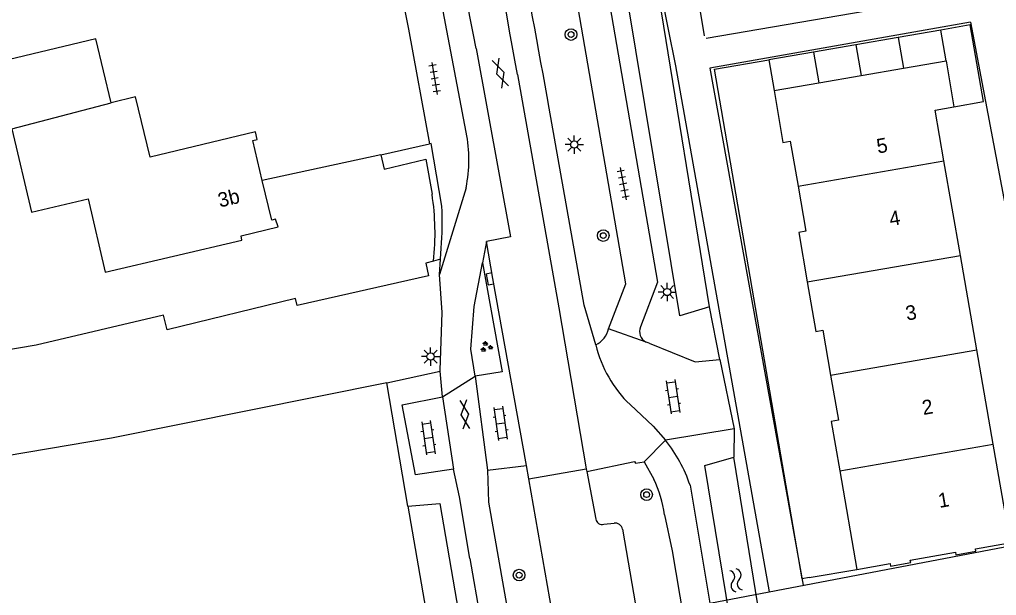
# Model space of a CAD drawing. Extents: x 136000 to 141000, y 400494 to 402006.
# Drawn here: x 137911.7 to 137978.9, y 401593.2 to 401632.8 of the extents above; entities that cross this region are included whole.
import ezdxf

# ---------------------------------------------------------------- set-up
doc = ezdxf.new("R2010")
doc.units = 0
for name, color, linetype in [('gg-afsc-erfafscheiding', 7, 'Continuous'), ('gg-afsc-hekwerk', 7, 'Continuous'), ('gg-anno-huisnummerreeks BGT', 7, 'Continuous'), ('gg-bbg-bijgebouw', 7, 'Continuous'), ('gg-bbg-hoofdgebouw', 7, 'Continuous'), ('gg-bbg-tussenscheiding', 7, 'Continuous'), ('gg-knt-bronhoudergrens', 7, 'Continuous'), ('gg-knt-plantopografie kant verharding', 7, 'Continuous'), ('gg-knt-verharding', 7, 'Continuous'), ('gg-knt-verharding nz', 7, 'Continuous'), ('gg-kntw-bovenkant insteek waterloop', 7, 'Continuous'), ('gt-grn-groengrens', 7, 'Continuous'), ('gt-grn-vlakafsluiter', 7, 'Continuous'), ('gt-grn-weggrens', 7, 'Continuous'), ('gt-symb-boom', 7, 'Continuous'), ('gt-symb-gesloten verharding', 7, 'Continuous'), ('gt-symb-groenvak', 7, 'Continuous'), ('gt-symb-klinker verharding', 7, 'Continuous'), ('gt-symb-kolk', 7, 'Continuous'), ('gt-symb-lichtmast', 7, 'Continuous'), ('gt-symb-tegel verharding', 7, 'Continuous'), ('gt-symb-watersymbool', 7, 'Continuous')]:
    doc.layers.add(name, color=color, linetype=linetype)

# ---------------------------------------------------------------- blocks, each defined once
blk = doc.blocks.new('gt0-TEG1')
at = {"layer": 'gt-symb-tegel verharding'}
for p, q in [((-1.125, 0), (1.125, 0)), ((-0.9, -0.25), (-0.9, 0.25)), ((-0.45, -0.25), (-0.45, 0.25)), ((0, -0.25), (0, 0.25)), ((0.45, -0.25), (0.45, 0.25)), ((0.9, -0.25), (0.9, 0.25))]:
    blk.add_line(p, q, dxfattribs=at)
blk = doc.blocks.new('gt0-LMAST')
at = {"layer": 'gt-symb-lichtmast'}
for p, q in [((-0.182, 0.173), (-0.447, 0.438)), ((-0.005, 0.246), (-0.005, 0.621)), ((0.172, 0.173), (0.437, 0.438)), ((-0.255, -0.004), (-0.63, -0.004)), ((-0.182, -0.181), (-0.447, -0.446)), ((-0.005, -0.254), (-0.005, -0.629)), ((0.437, -0.446), (0.172, -0.181)), ((0.245, -0.004), (0.62, -0.004))]:
    blk.add_line(p, q, dxfattribs=at)
blk.add_circle((-0.005, -0.004), 0.25, dxfattribs=at)
blk = doc.blocks.new('gt0-GESVH1')
at = {"layer": 'gt-symb-gesloten verharding'}
for p, q in [((-0.992, -0.261), (0.008, 0.239)), ((0.008, -0.261), (-0.992, 0.239)), ((0.008, 0.239), (1.008, -0.261)), ((1.008, 0.239), (0.008, -0.261))]:
    blk.add_line(p, q, dxfattribs=at)
blk = doc.blocks.new('gt0-BOOM')
at = {"layer": 'gt-symb-boom'}
for radius in [0.4, 0.2]:
    blk.add_circle((0, 0), radius, dxfattribs=at)
blk = doc.blocks.new('gt0-KL1')
at = {"layer": 'gt-symb-klinker verharding'}
for p, q in [((-1.15, 0.3), (1.15, 0.3)), ((-1, -0.3), (-1, 0.3)), ((-0.5, 0.3), (-0.5, 0.45)), ((0, -0.3), (0, 0.3)), ((0.5, 0.3), (0.5, 0.45)), ((1, -0.3), (1, 0.3)), ((-1.15, -0.3), (1.15, -0.3)), ((-0.5, -0.45), (-0.5, -0.3)), ((0.5, -0.45), (0.5, -0.3))]:
    blk.add_line(p, q, dxfattribs=at)
blk = doc.blocks.new('gt0-GRVAK')
at = {"layer": 'gt-symb-groenvak'}
for p, q in [((-0.11, 0.189), (-0.228, 0.24)), ((-0.182, 0.153), (0.088, 0.153)), ((-0.091, 0.211), (-0.156, 0.322)), ((-0.047, 0.214), (-0.047, 0.393)), ((-0.004, 0.211), (0.061, 0.322)), ((0.015, 0.189), (0.133, 0.24)), ((0.262, -0.052), (0.197, 0.059)), ((0.305, -0.049), (0.305, 0.13)), ((0.349, -0.052), (0.414, 0.059)), ((-0.245, -0.228), (-0.363, -0.177)), ((-0.318, -0.264), (-0.047, -0.264)), ((-0.226, -0.206), (-0.291, -0.095)), ((-0.183, -0.203), (-0.183, -0.024)), ((-0.139, -0.206), (-0.074, -0.095)), ((-0.12, -0.228), (-0.002, -0.177)), ((0.243, -0.074), (0.125, -0.023)), ((0.17, -0.11), (0.441, -0.11)), ((0.368, -0.074), (0.486, -0.023))]:
    blk.add_line(p, q, dxfattribs=at)
blk = doc.blocks.new('gt0-KOLK')
at = {"layer": 'gt-symb-kolk'}
blk.add_lwpolyline([(0, 0), (0.375, 0), (0.375, 0.4), (-0.375, 0.4), (-0.375, 0), (0, 0)], dxfattribs=at)
blk = doc.blocks.new('gt0-WA')
at = {"layer": 'gt-symb-watersymbool'}
for centre, start, end in [((-0.323, 0.022), 28.07249, 151.92751), ((0.427, 0.422), 208.07248, 331.92751), ((-0.323, -0.428), 28.07249, 151.92751), ((0.427, -0.028), 208.07248, 331.92751)]:
    blk.add_arc(centre, 0.425, start, end, dxfattribs=at)

msp = doc.modelspace()

# ---------------------------------------------------------------- linework, layer by layer
at = {"layer": 'gg-afsc-erfafscheiding'}
msp.add_line((137966.06, 401594.399), (137969.323, 401594.961), dxfattribs=at)
msp.add_lwpolyline([(137912.888, 401610.381), (137910.438, 401609.983), (137907.08, 401624.313), (137910.382, 401625.087)], dxfattribs=at)
at = {"layer": 'gg-afsc-hekwerk'}
msp.add_lwpolyline([(137930.707, 401613.611), (137921.883, 401611.435), (137921.643, 401612.459), (137912.888, 401610.381)], dxfattribs=at)
at = {"layer": 'gg-bbg-bijgebouw'}
msp.add_lwpolyline([(137918.035, 401627.072), (137916.985, 401631.468), (137909.296, 401629.631), (137910.382, 401625.087)], dxfattribs=at)
at = {"layer": 'gg-bbg-hoofdgebouw'}
for p, q in [((137972.166, 401631.564), (137969.259, 401631.061)), ((137975.102, 401632.072), (137972.166, 401631.564)), ((137969.259, 401631.061), (137966.352, 401630.558)), ((137966.352, 401630.558), (137963.279, 401630.026)), ((137963.279, 401630.026), (137963.638, 401627.918)), ((137976.45, 401616.57), (137975.321, 401623.074)), ((137977.578, 401610.073), (137976.45, 401616.57)), ((137978.706, 401603.577), (137977.578, 401610.073)), ((137968.154, 401601.745), (137969.323, 401594.961))]:
    msp.add_line(p, q, dxfattribs=at)
for points in [[(137976.011, 401626.789), (137978.048, 401627.155), (137977.13, 401632.423), (137975.102, 401632.072)], [(137928.434, 401621.724), (137927.78, 401624.461), (137928.085, 401624.546), (137927.955, 401625.064), (137920.709, 401623.331), (137919.718, 401627.474), (137918.035, 401627.072)], [(137963.638, 401627.918), (137964.248, 401624.342), (137964.747, 401624.428), (137965.282, 401621.33)], [(137975.321, 401623.074), (137974.716, 401626.557), (137976.011, 401626.789)], [(137911.21, 401625.281), (137912.553, 401619.546), (137916.448, 401620.458), (137917.628, 401615.414), (137927.032, 401617.615), (137926.974, 401617.904), (137929.517, 401618.533), (137929.351, 401619.051), (137929.088, 401618.988), (137928.434, 401621.724)], [(137965.282, 401621.33), (137965.817, 401618.233), (137965.33, 401618.145), (137965.914, 401614.74)], [(137965.914, 401614.74), (137966.497, 401611.335), (137966.993, 401611.421), (137967.528, 401608.328)], [(137967.528, 401608.328), (137968.062, 401605.235), (137967.569, 401605.139), (137968.154, 401601.745)], [(137969.323, 401594.961), (137971.61, 401595.36), (137971.642, 401595.179), (137973.039, 401595.425), (137973.008, 401595.604), (137976.111, 401596.146), (137976.141, 401595.973), (137977.51, 401596.215), (137977.48, 401596.385), (137983.184, 401597.381), (137983.098, 401597.873), (137979.799, 401597.285), (137978.706, 401603.577)]]:
    msp.add_lwpolyline(points, dxfattribs=at)
at = {"layer": 'gg-bbg-tussenscheiding'}
for p, q in [((137972.166, 401631.564), (137972.53, 401629.447)), ((137975.467, 401629.952), (137975.102, 401632.072)), ((137969.259, 401631.061), (137969.623, 401628.947)), ((137966.352, 401630.558), (137966.715, 401628.447)), ((137969.623, 401628.947), (137972.53, 401629.447)), ((137972.53, 401629.447), (137975.467, 401629.952)), ((137975.467, 401629.952), (137976.011, 401626.789)), ((137966.715, 401628.447), (137969.623, 401628.947)), ((137963.638, 401627.918), (137966.715, 401628.447)), ((137911.21, 401625.281), (137918.035, 401627.072)), ((137965.282, 401621.33), (137975.321, 401623.074)), ((137965.914, 401614.74), (137976.45, 401616.57)), ((137967.528, 401608.328), (137977.578, 401610.073)), ((137968.154, 401601.745), (137978.706, 401603.577))]:
    msp.add_line(p, q, dxfattribs=at)
at = {"layer": 'gg-knt-bronhoudergrens'}
msp.add_lwpolyline([(137936.993, 401607.793), (137918.069, 401603.99), (137899.215, 401600.795), (137896.666, 401600.542)], dxfattribs=at)
at = {"layer": 'gg-knt-plantopografie kant verharding'}
for p, q in [((137958.856, 401631.675), (137953.807, 401661.522)), ((137978.355, 401634.817), (137958.954, 401631.48)), ((137977.151, 401632.611), (137959.217, 401629.446)), ((137977.151, 401632.611), (137983.788, 401597.329)), ((137963.328, 401593.408), (137956.887, 401629.604)), ((137959.217, 401629.446), (137965.628, 401593.876)), ((137959.22, 401592.642), (137983.788, 401597.329))]:
    msp.add_line(p, q, dxfattribs=at)
msp.add_lwpolyline([(137956.887, 401629.604), (137952.664, 401650.546), (137952.218, 401652.545), (137951.83, 401653.881), (137951.177, 401656.389), (137950.331, 401659.075), (137949.399, 401661.212)], dxfattribs=at)
at = {"layer": 'gg-knt-verharding'}
for p, q in [((137936.579, 401623.494), (137939.94, 401624.245)), ((137942.448, 401621.224), (137940.623, 401615.243)), ((137943.851, 401617.527), (137943.572, 401616.054)), ((137940.685, 401616.296), (137940.731, 401617.063)), ((137940.685, 401616.296), (137940.202, 401616.178)), ((137940.623, 401615.243), (137940.685, 401616.296)), ((137954.835, 401610.597), (137952.237, 401611.521)), ((137955.043, 401610.523), (137954.835, 401610.597)), ((137959.907, 401609.394), (137960.9, 401604.633)), ((137940.826, 401606.846), (137940.678, 401608.593)), ((137943.065, 401608.252), (137943.928, 401601.784)), ((137940.826, 401606.846), (137941.594, 401601.858)), ((137960.9, 401604.633), (137956.171, 401603.844)), ((137943.928, 401601.784), (137946.603, 401602.119)), ((137946.76, 401601.199), (137946.603, 401602.119)), ((137954.705, 401602.369), (137955.361, 401601.176)), ((137943.928, 401601.784), (137944.001, 401599.598)), ((137946.76, 401601.199), (137950.718, 401601.872)), ((137950.718, 401601.872), (137950.764, 401601.707)), ((137950.764, 401601.707), (137951.37, 401598.426)), ((137957.855, 401600.749), (137959.22, 401592.642)), ((137944.001, 401599.598), (137947.295, 401580.773)), ((137956.095, 401598.709), (137956.624, 401596.244)), ((137951.922, 401598.067), (137952.637, 401598.134)), ((137956.624, 401596.244), (137958.787, 401583.372)), ((137942.71, 401595.71), (137955.74, 401521.282))]:
    msp.add_line(p, q, dxfattribs=at)
for points in [[(137942.461, 401625.036), (137940.244, 401636.649), (137938.433, 401645.965), (137936.328, 401656.277), (137932.589, 401672.987), (137932.577, 401673.206)], [(137934.692, 401650.955), (137936.474, 401642.178), (137938.479, 401632.133), (137939.94, 401624.245)], [(137949.745, 401648.773), (137955.606, 401614.715), (137954.453, 401611.654)], [(137952.237, 401611.521), (137953.444, 401614.609), (137947.889, 401646.77)], [(137951.375, 401610.407), (137950.567, 401613.137), (137948.167, 401626.703)], [(137940.785, 401619.95), (137940.06, 401624.266), (137939.94, 401624.245)], [(137936.827, 401622.491), (137939.674, 401623.195), (137940.109, 401620.773)], [(137946.603, 401602.119), (137944.291, 401614.987), (137943.851, 401617.527)], [(137940.202, 401616.178), (137939.69, 401616.042), (137939.862, 401615.157), (137930.822, 401613.128), (137930.707, 401613.611)], [(137943.065, 401608.252), (137942.787, 401610.105), (137943.009, 401613.042), (137943.572, 401616.054)], [(137943.572, 401616.054), (137944.922, 401608.553), (137943.065, 401608.252)], [(137940.678, 401608.593), (137940.671, 401608.681), (137940.803, 401612.643), (137940.623, 401615.243)], [(137955.043, 401610.523), (137958.21, 401609.252), (137959.907, 401609.394)], [(137941.594, 401601.858), (137938.972, 401601.458), (137938.045, 401606.284), (137940.826, 401606.846)], [(137953.73, 401606.296), (137955.31, 401604.809), (137956.171, 401603.844)], [(137950.764, 401601.707), (137954.037, 401602.387), (137954.096, 401602.267), (137954.705, 401602.369)], [(137942.71, 401595.71), (137941.999, 401599.953), (137941.594, 401601.858)], [(137949.373, 401586.296), (137948.38, 401592.013), (137946.76, 401601.199)], [(137953.206, 401597.734), (137954.115, 401592.532), (137955.8, 401582.708)]]:
    msp.add_lwpolyline(points, dxfattribs=at)
for centre, radius, start, end in [((136946.771, 401448.506), 1017.127, 10.090092, 11.527453), ((137932.913, 401623.163), 9.73, 348.50794, 11.10127), ((137923.259, 401618.134), 17.055, 353.41612, 8.90283), ((137921.508, 401618.867), 19.307, 354.63996, 3.2169), ((137950.699, 401611.82), 1.566, 295.54956, 348.98588), ((137955.211, 401611.33), 0.824, 156.88423, 242.8555), ((137959.586, 401612.381), 8.445, 193.51573, 226.09703), ((137948.345, 401597.58), 10.024, 18.42865, 38.67288), ((137948.547, 401597.806), 7.602, 6.82249, 26.31587), ((137951.801, 401598.485), 0.435, 187.76491, 286.15817), ((137952.729, 401597.66), 0.483, 8.80897, 100.97754)]:
    msp.add_arc(centre, radius, start, end, dxfattribs=at)
at = {"layer": 'gg-knt-verharding nz'}
for points in [[(137943.141, 401630.806), (137945.508, 401617.855), (137943.851, 401617.527)], [(137945.981, 401629.023), (137948.841, 401612.955), (137950.718, 401601.872)]]:
    msp.add_lwpolyline(points, dxfattribs=at)
for centre, radius, start, end in [((136145.633, 401282.114), 1831.017, 10.978255, 11.929262), ((137074.99, 401473.734), 884.725, 10.109038, 12.188098)]:
    msp.add_arc(centre, radius, start, end, dxfattribs=at)
at = {"layer": 'gg-kntw-bovenkant insteek waterloop'}
for p, q in [((137959.199, 401613.018), (137954.757, 401640.372)), ((137957.162, 401612.408), (137952.586, 401640.019)), ((137959.199, 401613.018), (137957.162, 401612.408)), ((137958.868, 401602.108), (137960.876, 401602.691)), ((137974.186, 401509.676), (137958.868, 401602.108)), ((137938.451, 401599.318), (137952.459, 401517.688))]:
    msp.add_line(p, q, dxfattribs=at)
for points in [[(137976.365, 401510.046), (137966.124, 401570.369), (137960.876, 401602.691)], [(137938.451, 401599.318), (137940.655, 401599.486), (137954.628, 401518.063)]]:
    msp.add_lwpolyline(points, dxfattribs=at)
at = {"layer": 'gt-grn-groengrens'}
for p, q in [((137959.907, 401609.394), (137959.199, 401613.018)), ((137936.993, 401607.793), (137940.678, 401608.593)), ((137938.451, 401599.318), (137936.993, 401607.793)), ((137960.9, 401604.633), (137960.876, 401602.691))]:
    msp.add_line(p, q, dxfattribs=at)
at = {"layer": 'gt-grn-vlakafsluiter'}
for q in [(137928.434, 401621.724), (137936.827, 401622.491)]:
    msp.add_line((137936.579, 401623.494), q, dxfattribs=at)
msp.add_lwpolyline([(137966.06, 401594.399), (137965.578, 401594.315), (137959.535, 401629.377), (137963.279, 401630.026)], dxfattribs=at)
at = {"layer": 'gt-grn-weggrens'}
for p, q in [((137940.826, 401606.846), (137943.065, 401608.252)), ((137954.705, 401602.369), (137956.171, 401603.844))]:
    msp.add_line(p, q, dxfattribs=at)

# ---------------------------------------------------------------- block references
at = {"layer": 'gt-symb-boom'}
for p in [(137949.668, 401631.762), (137951.889, 401617.929), (137954.869, 401600.105), (137946.098, 401594.569)]:
    msp.add_blockref('gt0-BOOM', p, dxfattribs=at)
at = {"layer": 'gt-symb-gesloten verharding'}
for p, rotation in [((137944.798, 401629.094), 108.59797779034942), ((137942.354, 401605.611), 95.79610065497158)]:
    msp.add_blockref('gt0-GESVH1', p, dxfattribs=dict(at, rotation=rotation))
at = {"layer": 'gt-symb-groenvak'}
msp.add_blockref('gt0-GRVAK', (137943.834, 401610.269), dxfattribs=at)
at = {"layer": 'gt-symb-klinker verharding'}
for p, rotation in [((137956.686, 401606.841), -81.78079075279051), ((137944.819, 401605.01), -81.78079075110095), ((137939.858, 401604.017), -81.78079075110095)]:
    msp.add_blockref('gt0-KL1', p, dxfattribs=dict(at, rotation=rotation))
at = {"layer": 'gt-symb-kolk', "rotation": 100.1893600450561}
msp.add_blockref('gt0-KOLK', (137944.291, 401614.987), dxfattribs=at)
at = {"layer": 'gt-symb-lichtmast'}
for p in [(137949.9, 401624.194), (137956.29, 401614.05), (137940.017, 401609.605)]:
    msp.add_blockref('gt0-LMAST', p, dxfattribs=at)
at = {"layer": 'gt-symb-tegel verharding'}
for p, rotation in [((137940.292, 401628.738), 99.37757912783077), ((137953.258, 401621.502), -79.16208955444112)]:
    msp.add_blockref('gt0-TEG1', p, dxfattribs=dict(at, rotation=rotation))
at = {"layer": 'gt-symb-watersymbool', "rotation": 106.0241096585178}
msp.add_blockref('gt0-WA', (137961.032, 401594.16), dxfattribs=at)

# ---------------------------------------------------------------- texts
at = {"layer": 'gg-anno-huisnummerreeks BGT'}
for s, rotation, p in [('5', 9.9, (137970.78, 401623.571)), ('3b', 13.5, (137925.513, 401619.853)), ('4', 9.9, (137971.648, 401618.577)), ('3', 9.9, (137972.776, 401612.077)), ('2', 9.9, (137973.904, 401605.581)), ('1', 9.9, (137975.015, 401599.187))]:
    msp.add_text(s, height=1, rotation=rotation, dxfattribs=at).set_placement(p)

doc.saveas('drawing.dxf')
